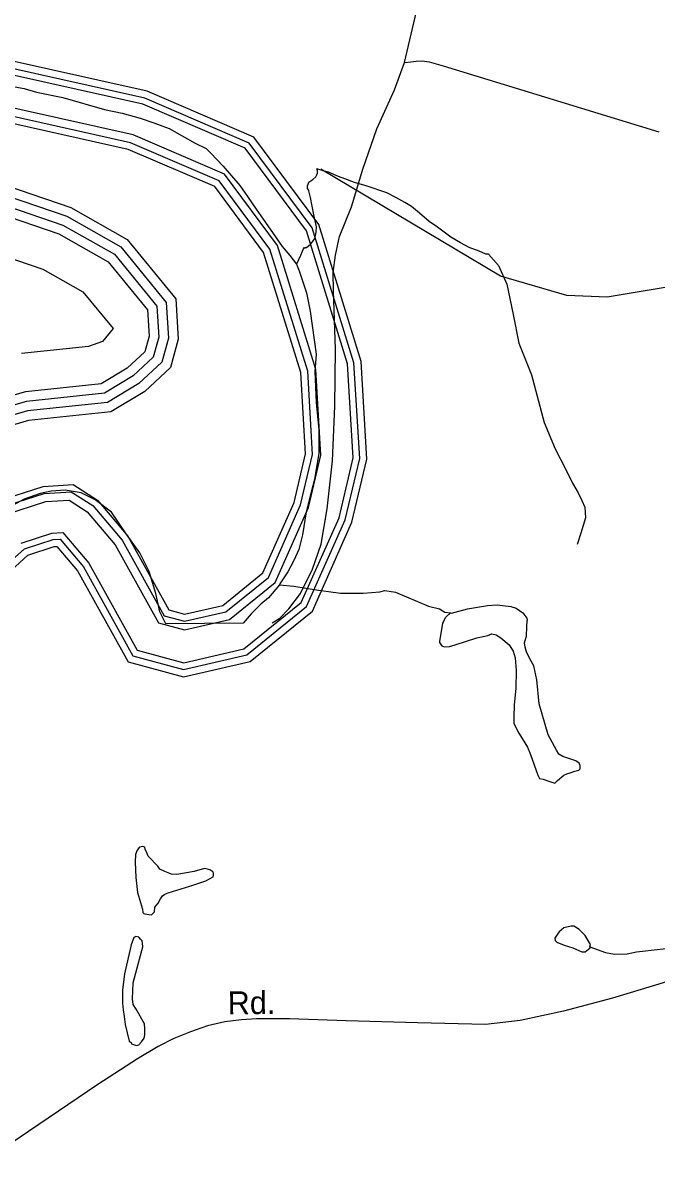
# Model space of a CAD drawing. Extents: x 2260773 to 2342389, y 552869 to 618546.
# Drawn here: x 2280360 to 2282991, y 590512 to 595296 of the extents above; entities that cross this region are included whole.
import ezdxf

# ---------------------------------------------------------------- set-up
doc = ezdxf.new("R2010")
doc.units = 0
for name, color, linetype in [('Exist Hydrographic Buffer Line', 7, 'Continuous'), ('Exist Hydrographic Lake Shore', 7, 'Continuous'), ('Exist Hydrographic Misc Water Feature', 7, 'Continuous'), ('Exist Hydrographic River Shore', 7, 'Continuous'), ('Exist Road Non-System Type 51', 7, 'Continuous'), ('Exist Road Secondary Type 51 Attributed', 7, 'Continuous'), ('Exist Road Secondary Type 51 Label', 7, 'Continuous')]:
    doc.layers.add(name, color=color, linetype=linetype)

msp = doc.modelspace()

# ---------------------------------------------------------------- linework, layer by layer
at = {"layer": 'Exist Hydrographic Buffer Line'}
for points in [[(2280351.6, 593135.8), (2280479.2, 593177.1), (2280525.4, 593179.8), (2280632.4, 593052.5), (2280833.6, 592691.1), (2281027, 592639.2), (2281276.8, 592696.5), (2281514.9, 592889.1), (2281671.5, 593241.5), (2281730.4, 593489.7), (2281707.2, 593880.4), (2281536.2, 594433.6), (2281281.7, 594775.9), (2280857.6, 594958.9), (2280050.9, 595138.8)], [(2280288, 593043), (2280365.2, 593112.1), (2280484.2, 593150.5), (2280513.6, 593152.2), (2280610.2, 593037.2), (2280815.7, 592668.2), (2281026.5, 592611.6), (2281288.8, 592671.7), (2281536.8, 592872.3), (2281697, 593232.9), (2281757.4, 593487.4), (2281733.7, 593885.2), (2281560.5, 594445.9), (2281299, 594797.6), (2280865.9, 594984.5), (2280052.8, 595165.8)], [(2280283.9, 593253.9), (2280454.4, 593309), (2280551, 593314.7), (2280626.5, 593266.5), (2280742.5, 593128.4), (2280922.6, 592805.2), (2281029.5, 592776.4), (2281217, 592819.4), (2281406.2, 592972.5), (2281544.8, 593284.2), (2281596.3, 593501.4), (2281575.2, 593856.4), (2281415.7, 594372.4), (2281196.2, 594667.7), (2280816.3, 594831.7), (2280041.2, 595004.5)], [(2280266.5, 593284.1), (2280448.1, 593342.8), (2280560.1, 593349.4), (2280649.3, 593292.5), (2280770.8, 593147.9), (2280945.4, 592834.4), (2281030.2, 592811.6), (2281201.7, 592850.9), (2281378.4, 592993.9), (2281512.3, 593295.2), (2281561.9, 593504.4), (2281541.4, 593850.3), (2281384.9, 594356.8), (2281174.3, 594640), (2280805.8, 594799.1), (2280038.8, 594970.1)], [(2280171, 594620.2), (2280541.3, 594493.6), (2280765.4, 594366.5), (2280954.5, 594135.5), (2280963.5, 593987.5), (2280936.2, 593887.4), (2280840.5, 593798.5), (2280710.7, 593719.6), (2280378.5, 593684.8), (2280105.8, 593606.8)], [(2280161.1, 594581.3), (2280524.7, 594457), (2280739.2, 594335.4), (2280915.5, 594120.2), (2280922.9, 593991.7), (2280900.5, 593909), (2280816.3, 593830.5), (2280697.5, 593758.4), (2280374.4, 593724.6), (2280094.5, 593645.3)], [(2280151.5, 594542.4), (2280508.3, 594420.3), (2280712.9, 594304.2), (2280876.1, 594104.8), (2280882.7, 593995.8), (2280864.9, 593930.5), (2280791.9, 593862.6), (2280684.4, 593797.3), (2280370.3, 593764.4), (2280083.4, 593683.7)], [(2280112.5, 594386.6), (2280442.5, 594273.7), (2280608.1, 594179.8), (2280734.4, 594027.7), (2280690, 593972.8), (2280631.9, 593952.6), (2280353.5, 593923.5)]]:
    msp.add_lwpolyline(points, dxfattribs=at)
at = {"layer": 'Exist Hydrographic Lake Shore'}
msp.add_lwpolyline([(2280180.6, 594659.1), (2280557.7, 594530.2), (2280791.7, 594397.6), (2280993.6, 594150.8), (2281003.7, 593983.3), (2280971.7, 593865.9), (2280864.7, 593766.4), (2280723.8, 593680.7), (2280382.8, 593645), (2280116.6, 593568.4)], dxfattribs=at)
at = {"layer": 'Exist Hydrographic Misc Water Feature'}
for p, q in [((2282135, 592845.9), (2282139.1, 592845.3)), ((2281273.9, 592803.6), (2280952.2, 592800.6))]:
    msp.add_line(p, q, dxfattribs=at)
for points in [[(2280287.4, 595037.5), (2280365.1, 595024.2), (2280415.2, 595008.5), (2280525.5, 594987.4), (2280697.9, 594937.1), (2280771.8, 594921.9), (2280846, 594900.6), (2280902.4, 594881.2), (2280966.4, 594857.7), (2281074.8, 594796.8), (2281119.3, 594775.5), (2281139.4, 594755.4), (2281190.1, 594702), (2281260.2, 594620.8), (2281291, 594575.3), (2281327.3, 594523.6), (2281366, 594467.8), (2281398.4, 594422)], [(2281525.1, 594363.6), (2281529, 594361.4), (2281532.7, 594363.6), (2281537, 594363.4), (2281553, 594377.6), (2281561, 594387.8), (2281570.7, 594401.8), (2281576.2, 594427.6), (2281578, 594449.7), (2281567.4, 594499.6), (2281553, 594571.5), (2281546.5, 594599.6), (2281544.2, 594603.6), (2281540.5, 594609.4), (2281540.7, 594615.5), (2281540.5, 594619.6), (2281542.8, 594627.4), (2281544.2, 594631.6), (2281546, 594635.4), (2281550.3, 594637.6), (2281562.2, 594645.5), (2281575.8, 594657.7), (2281579.7, 594666), (2281581.9, 594671.8), (2281582.1, 594677.8), (2281581.9, 594683.9), (2281579.9, 594689.9)], [(2282292.4, 594336.7), (2282280.5, 594336.5), (2282252.9, 594348.4), (2282212.5, 594363.8), (2282176.2, 594383.5), (2282136.4, 594407.3), (2282080, 594448.7), (2282045.6, 594472.1), (2282005.2, 594505.8), (2281973, 594533.8), (2281944.9, 594551.3), (2281906.9, 594570.9), (2281870.6, 594590.5), (2281788, 594618), (2281736.1, 594633.5), (2281695.9, 594648.9), (2281669.9, 594658.5), (2281627.7, 594676.2), (2281605.7, 594682), (2281579.9, 594689.9)], [(2284564.8, 592838.8), (2283617.7, 593241.7), (2283499.8, 593322.8), (2283373.7, 593489.3), (2283362.8, 593755.2), (2283435.8, 593957), (2283426.8, 594088.4), (2283166.8, 594221.6), (2282784.8, 594157.2), (2282617.6, 594163.8), (2282341.6, 594244.8), (2281596.7, 594689.5)], [(2281398.4, 594422), (2281434.9, 594368.6), (2281467.3, 594330.9), (2281495.4, 594295.1)], [(2281525.1, 594363.6), (2281511.2, 594331.2), (2281495.4, 594295.1)], [(2282292.4, 594336.7), (2282333.4, 594289.2), (2282367.7, 594211.5), (2282394.8, 594085.8), (2282418.3, 593966.2), (2282471.2, 593834.6), (2282523.3, 593637.3), (2282568.4, 593527.5), (2282611.1, 593444.1), (2282641.4, 593384.7), (2282664.2, 593344.8), (2282680.2, 593312.8), (2282692.5, 593285), (2282695, 593241.2), (2282675.3, 593176.9), (2282660.1, 593130.9)], [(2281495.4, 594295.1), (2281505.6, 594267.1), (2281536.8, 594175.7), (2281551.4, 594099.7), (2281577.2, 593920.2), (2281571.5, 593848.1), (2281577, 593720.3), (2281587.9, 593606.4), (2281587.1, 593510.3), (2281570, 593400.5), (2281556.3, 593348.3), (2281535, 593266.3), (2281520.2, 593170), (2281504.6, 593109.9), (2281483.5, 593063.6), (2281459.5, 593017.3), (2281426.1, 592967.2), (2281424.2, 592963.1)], [(2280952.2, 592800.6), (2280927.4, 592850.6), (2280910.6, 592926.5), (2280883.7, 593018.1), (2280845.2, 593095.7), (2280788.4, 593175.2), (2280727.5, 593264.3), (2280659.2, 593315.9), (2280600.8, 593345.4), (2280535.1, 593356.5), (2280476.9, 593351.9), (2280431, 593341.8), (2280365.1, 593318.9), (2280282.1, 593274.2), (2280218.5, 593223.8), (2280163, 593169.3), (2280119.5, 593106.9), (2280090.2, 593050.5), (2280066.6, 593000.5), (2280030.9, 592930), (2280011.8, 592853.9), (2280004.5, 592791.7)], [(2281424.2, 592963.1), (2281378.5, 592908.7), (2281346.9, 592882.6), (2281307.2, 592842.4), (2281273.9, 592803.6)], [(2281424.2, 592963.1), (2281484.1, 592957.7), (2281586.2, 592940.7), (2281628.3, 592935.2), (2281678.3, 592927.6), (2281772, 592928.5), (2281840.5, 592933.2), (2281862.2, 592939.3), (2281906.5, 592931.8), (2282042.7, 592874.7), (2282088.8, 592862.9), (2282110.8, 592849.1), (2282135, 592845.9)], [(2282139.1, 592845.3), (2282204.5, 592863.8), (2282288.3, 592876.7), (2282328.7, 592879.1), (2282384.7, 592873.5), (2282406.4, 592865.8), (2282434.9, 592846.1), (2282450.9, 592824.2), (2282453, 592814.1)], [(2282105.2, 592811), (2282115.1, 592828.9), (2282135, 592845.9)], [(2282105.2, 592811), (2282101.3, 592803.1), (2282093.9, 592760.8), (2282088.2, 592728.8), (2282088, 592722.7), (2282094.4, 592714.9), (2282098, 592709), (2282108.5, 592705), (2282130, 592707.1), (2282154, 592713.6), (2282243.8, 592742.3), (2282289.8, 592752.8), (2282305.8, 592758.9), (2282323.8, 592754.9), (2282343.9, 592743), (2282377.9, 592713.5), (2282394.1, 592688), (2282402.8, 592659.9), (2282407.3, 592607.7), (2282405.6, 592532.1), (2282398.4, 592463.9), (2282396.6, 592413.9), (2282397, 592387.9), (2282413.4, 592354.2), (2282454, 592288.4), (2282466.3, 592258.6), (2282497.1, 592172.8), (2282503.4, 592158.9), (2282519.2, 592155.3), (2282539.1, 592149.5), (2282567.2, 592139.6), (2282579.1, 592149.9), (2282604.9, 592172), (2282617, 592177.9), (2282631, 592182.3), (2282650.7, 592188.3), (2282666.7, 592192.7), (2282672.8, 592198.7), (2282672.4, 592212.5), (2282668.7, 592222.5), (2282654.6, 592232.2), (2282600, 592249.8), (2282584.2, 592259.9), (2282573.8, 592275.7), (2282539.3, 592339.2), (2282502.2, 592468.9), (2282493.4, 592568.8), (2282480.9, 592626.7), (2282462.4, 592658.2), (2282450.5, 592684.3), (2282444.2, 592704.4), (2282441.9, 592722.1), (2282449.5, 592750.2), (2282451.1, 592788), (2282453, 592814.1)], [(2280834.5, 591685.7), (2280855.2, 591616), (2280857.3, 591602), (2280861.2, 591598.1), (2280865.5, 591595.8), (2280881.5, 591594.3), (2280893.4, 591592.4), (2280897.5, 591596.3), (2280905.3, 591604.5), (2280906.9, 591624.5), (2280921, 591640.6), (2280930.7, 591658.6), (2280938.7, 591670.8), (2280948.5, 591678.6), (2280962.5, 591683), (2281052.3, 591711.7), (2281118.1, 591734.2), (2281149.7, 591750.5), (2281149.9, 591756.6), (2281149.9, 591764.7), (2281147.4, 591770.7), (2281135.7, 591778.6), (2281113.2, 591784.4), (2281069.9, 591771.9), (2280997.7, 591759.2), (2280975.8, 591760.9), (2280947.7, 591772.8), (2280927.6, 591782.4), (2280919.4, 591794.6), (2280879, 591835.9), (2280872.7, 591853.9), (2280866.7, 591863.7), (2280864.7, 591873.8), (2280856.9, 591875.8), (2280842.9, 591873.8), (2280832.9, 591861.5), (2280826.7, 591843.4), (2280825.3, 591811.5), (2280827.7, 591747.5), (2280834.5, 591685.7)], [(2282713.4, 591459.4), (2282715.5, 591469.6), (2282693.1, 591507), (2282669.1, 591530.9), (2282652.9, 591540.7), (2282646.8, 591544.9), (2282634.9, 591544.6), (2282604.9, 591538.2), (2282585.2, 591522.1), (2282581.1, 591516.2), (2282573.4, 591504), (2282567.2, 591496), (2282569.5, 591485.9), (2282575.4, 591478.2), (2282605.8, 591466.3), (2282641.6, 591454.8), (2282679.8, 591439.3), (2282693.7, 591439.2), (2282707.9, 591449.3), (2282713.8, 591455.3), (2282713.4, 591459.4)], [(2280791.7, 591101.6), (2280800.1, 591067.6), (2280808.5, 591061.8), (2280810.5, 591055.9), (2280830.4, 591050), (2280840.5, 591052.2), (2280852.1, 591064.2), (2280862.2, 591080.5), (2280865.7, 591094.2), (2280865.5, 591118.5), (2280863.6, 591140.3), (2280829, 591199.9), (2280816.9, 591219.9), (2280814.6, 591243.8), (2280816.3, 591309.7), (2280843.1, 591407.8), (2280856.5, 591460.1), (2280856.2, 591474), (2280854.6, 591484), (2280848.3, 591490.2), (2280840.3, 591499.9), (2280828.2, 591501.7), (2280820.2, 591497.6), (2280808.5, 591467.4), (2280781.6, 591347.3), (2280772.4, 591279.4), (2280772.8, 591225.3), (2280775.5, 591197.4), (2280779.8, 591169.6), (2280783.7, 591137.4), (2280791.7, 591101.6)], [(2282713.4, 591459.4), (2282777.8, 591435.9), (2282815.7, 591428.5), (2282868, 591430.8), (2282905.9, 591439.3), (2283103.4, 591461)]]:
    msp.add_lwpolyline(points, dxfattribs=at)
at = {"layer": 'Exist Hydrographic River Shore'}
for points in [[(2280311.2, 593024.4), (2280380.2, 593086), (2280489.6, 593121.4), (2280500.6, 593122), (2280585.9, 593020.5), (2280796.1, 592643), (2281025.9, 592581.3), (2281302, 592644.6), (2281560.8, 592853.9), (2281725, 593223.4), (2281787, 593484.8), (2281762.9, 593890.5), (2281587.1, 594459.4), (2281317.8, 594821.5), (2280875, 595012.6), (2280055, 595195.4)], [(2280251.8, 593309.8), (2280442.7, 593371.6), (2280567.7, 593378.9), (2280668.6, 593314.5), (2280794.7, 593164.4), (2280964.7, 592859.2), (2281030.7, 592841.5), (2281188.6, 592877.6), (2281354.7, 593012), (2281484.7, 593304.5), (2281532.7, 593506.9), (2281512.6, 593845.1), (2281358.6, 594343.5), (2281155.6, 594616.5), (2280796.8, 594771.4), (2280036.7, 594940.8)]]:
    msp.add_lwpolyline(points, dxfattribs=at)
at = {"layer": 'Exist Road Non-System Type 51'}
for points in [[(2281942.8, 595131.6), (2282077.6, 595703.2), (2282378.7, 596847.5), (2282559.8, 597582.8)], [(2281393.4, 592804.4), (2281425.2, 592824.5), (2281462.7, 592862.9), (2281512, 592927.3), (2281561, 593027.7), (2281598.1, 593132.1), (2281622.7, 593278.1), (2281644.8, 593478.4), (2281654.7, 593704.3), (2281656.4, 593942.2), (2281648.1, 594184.1), (2281647.4, 594259.9), (2281656.7, 594332.1), (2281674.1, 594410.1), (2281723.7, 594532.1), (2281770.2, 594689.3), (2281828.4, 594856.1), (2281902.1, 595018), (2281942.8, 595131.6)], [(2281942.8, 595131.6), (2281969.9, 595135.5), (2281991.3, 595137.5), (2282016.5, 595139.4), (2282045.6, 595135.5), (2282103.7, 595118.1), (2282999.6, 594844.5)]]:
    msp.add_lwpolyline(points, dxfattribs=at)
at = {"layer": 'Exist Road Secondary Type 51 Attributed'}
msp.add_lwpolyline([(2283031.1, 591313.5), (2282806.7, 591246.4), (2282603.3, 591191.8), (2282423, 591154), (2282279.3, 591137.3), (2281997.3, 591143.5), (2281700.6, 591151.9), (2281465.7, 591160.3), (2281329.4, 591160.3), (2281266.5, 591156.1), (2281197.3, 591147.7), (2281126, 591131), (2281054.7, 591105.8), (2280985.5, 591078.5), (2280920.5, 591044.9), (2280834.5, 590994.6), (2280669.9, 590887.6), (2280382.6, 590692.4), (2280117.3, 590512)], dxfattribs=at)

# ---------------------------------------------------------------- texts
at = {"layer": 'Exist Road Secondary Type 51 Label'}
msp.add_text('Rd.', height=95, rotation=0.535, dxfattribs=at).set_placement((2281209.9, 591179))

doc.saveas('drawing.dxf')
